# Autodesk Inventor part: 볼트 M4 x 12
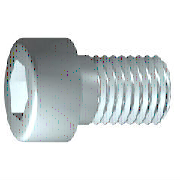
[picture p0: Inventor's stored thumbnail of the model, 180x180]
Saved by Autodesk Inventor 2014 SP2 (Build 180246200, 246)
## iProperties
IsCustomPart: 0
Created: 2012-02
Part Number: 볼트 M4 x 12
Material: 스테인리스강
Description: 6각 소켓 머리 캡 나사
Document SubType Name: Modeling
Standard: ISO 4762
Designer: mduedu
Standard Revision: Fourth edition 2004-03-01
Standards Organization: ISO
Language: ko-KR
Size Designation: M4 x 12
Categories: <MemberInstance><Categories><Category DisplayName="조임쇠" InternalName="e4da775c-781d-43d5-af7c-5136215cf5a6" Mnemonic="FSTN"><Category DisplayName="볼트" InternalN
Density: 8.08 g/cm^3
Appearance: 반광택
Author: mduedu
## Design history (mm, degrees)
sketch "스케치1"
  geometry: L1 (-1, 0)-(12, 0); L2 (12, 0)-(12, 2); L3 (12, 2)-(1.75, 2); L4 (1.75, 2)-(1.32, 2); L5 (1.32, 2)-(0, 2); L6 (0, 2)-(0, 3.5); L7 (0, 3.5)-(-4, 3.5); L8 (-4, 3.5)-(-4, 1.732); L9 (-4, 1.732)-(-2, 1.732); L10 (-2, 1.732)-(-1, 0); L11 (-7.2, 0)-(15.2, 0) reference; L12 (0, -0.7)-(0, 4.2) reference; L13 (1.75, 2)-(0, 2)
  constraints: 22 end point, 6 parallel, 2 collinear, 2 perpendicular, 1 horizontal, 1 point on line
  dimensions: "d1" = 10.25 distance from line of L3.end L2 (= GEL); "d2" = 0.42952 distance of L4.end L3.end (computed from GAL); "d3" = 4 distance between parallel lines of L8 L6 (= KOH); "d4" = 2 distance of L8.end L9.end (= INTI); "d5" = 60 deg angle of L10 L1; "d6" = 4 diameter of L3 L1 (= GD); "d7" = 4 diameter of L5 L1 (= BDM); "d8" = 3.4641 diameter of L9 L1 (= 1.1547 x SW); "d9" = 7 diameter of L7 L1 (= KOD); "d26" = 12 distance between parallel lines of L12 L2 (= NLG)
revolve "본체" sketch "스케치1" stored, may be unused: angle "d10" = 90 deg
sketch "스케치2"
  geometry: L1 (0, -4.9)-(0, 4.9) reference; L2 (-4.9, 0)-(4.9, 0) reference; L3 (1.732, 0)-(0.866, -1.5); L4 (0.866, -1.5)-(-0.866, -1.5); L5 (-0.866, -1.5)-(-1.732, 0); L6 (-1.732, 0)-(-0.866, 1.5); L7 (-0.866, 1.5)-(0.866, 1.5); L8 (0.866, 1.5)-(1.732, 0); 2 further points
  constraints: 12 end point, 1 coincident, 1 horizontal alignment, 1 point on line, 12 other
extrude "슬롯" join sketch "스케치2" stored distance "d11" = 10; taper "d12" = 0 deg
workplane "Work Plane1"
fillet "Fillet2" dims "d30" = 0.1 (= R)
body "Solid1"
fillet "모깎기1" dims "d17" = 0.4 (= RR)
feature "스레드" dims "d13" = 10.25 (= GEL), "d14" = 0
chamfer "모따기1" distance "d15" = 0.42941 (= -0.5 x SPD + 0.5 x GD); stored, may be unused: second distance "d16" = 0.42941 (= GUL), angle "d27" = 45 deg
other parameters: "GD" = 4 [user parameter; used in 2 equation terms], "NLG" = 12 [user parameter; used in 1 equation term], "GEL" = 10.25 [user parameter; used in 2 equation terms], "KOD" = 7 [user parameter; used in 1 equation term], "KOH" = 4 [user parameter; used in 1 equation term], "INTI" = 2 [user parameter; used in 1 equation term], "GAL" = 0.42941 (= 0.61345 x PTC) [user parameter; used in 1 equation term], "GUL" = 0.42941 (= 0.61345 x PTC) [user parameter; used in 1 equation term], "BDM" = 4 (= NND) [user parameter; used in 1 equation term], "SW" = 3 [user parameter; used in 2 equation terms], "RR" = 0.4 [user parameter; used in 1 equation term], "SPD" = 3.14117 (= NND - 1.2269 x PTC) [user parameter; used in 1 equation term], "d19" = 0, "d28" = 0, "d29" = 0, "R" = 0.1 [user parameter; used in 1 equation term], "TOA" = 30 deg [user parameter], "GD1" = 3.14117 (= THREADDIA - 1.2269 x PTC) [user parameter], "THREADDIA" = 4 [user parameter; used in 1 equation term], "FAWI" = 45 deg [user parameter], "TPU" = 14.28571 (computed from PTC) [user parameter], "PTC" = 0.7 [user parameter; used in 5 equation terms], "NND" = 4 [user parameter; used in 2 equation terms], "E0" = 3.465 (= 1.155 x SW) [user parameter]
